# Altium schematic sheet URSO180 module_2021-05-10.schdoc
size 355 x 391 mm
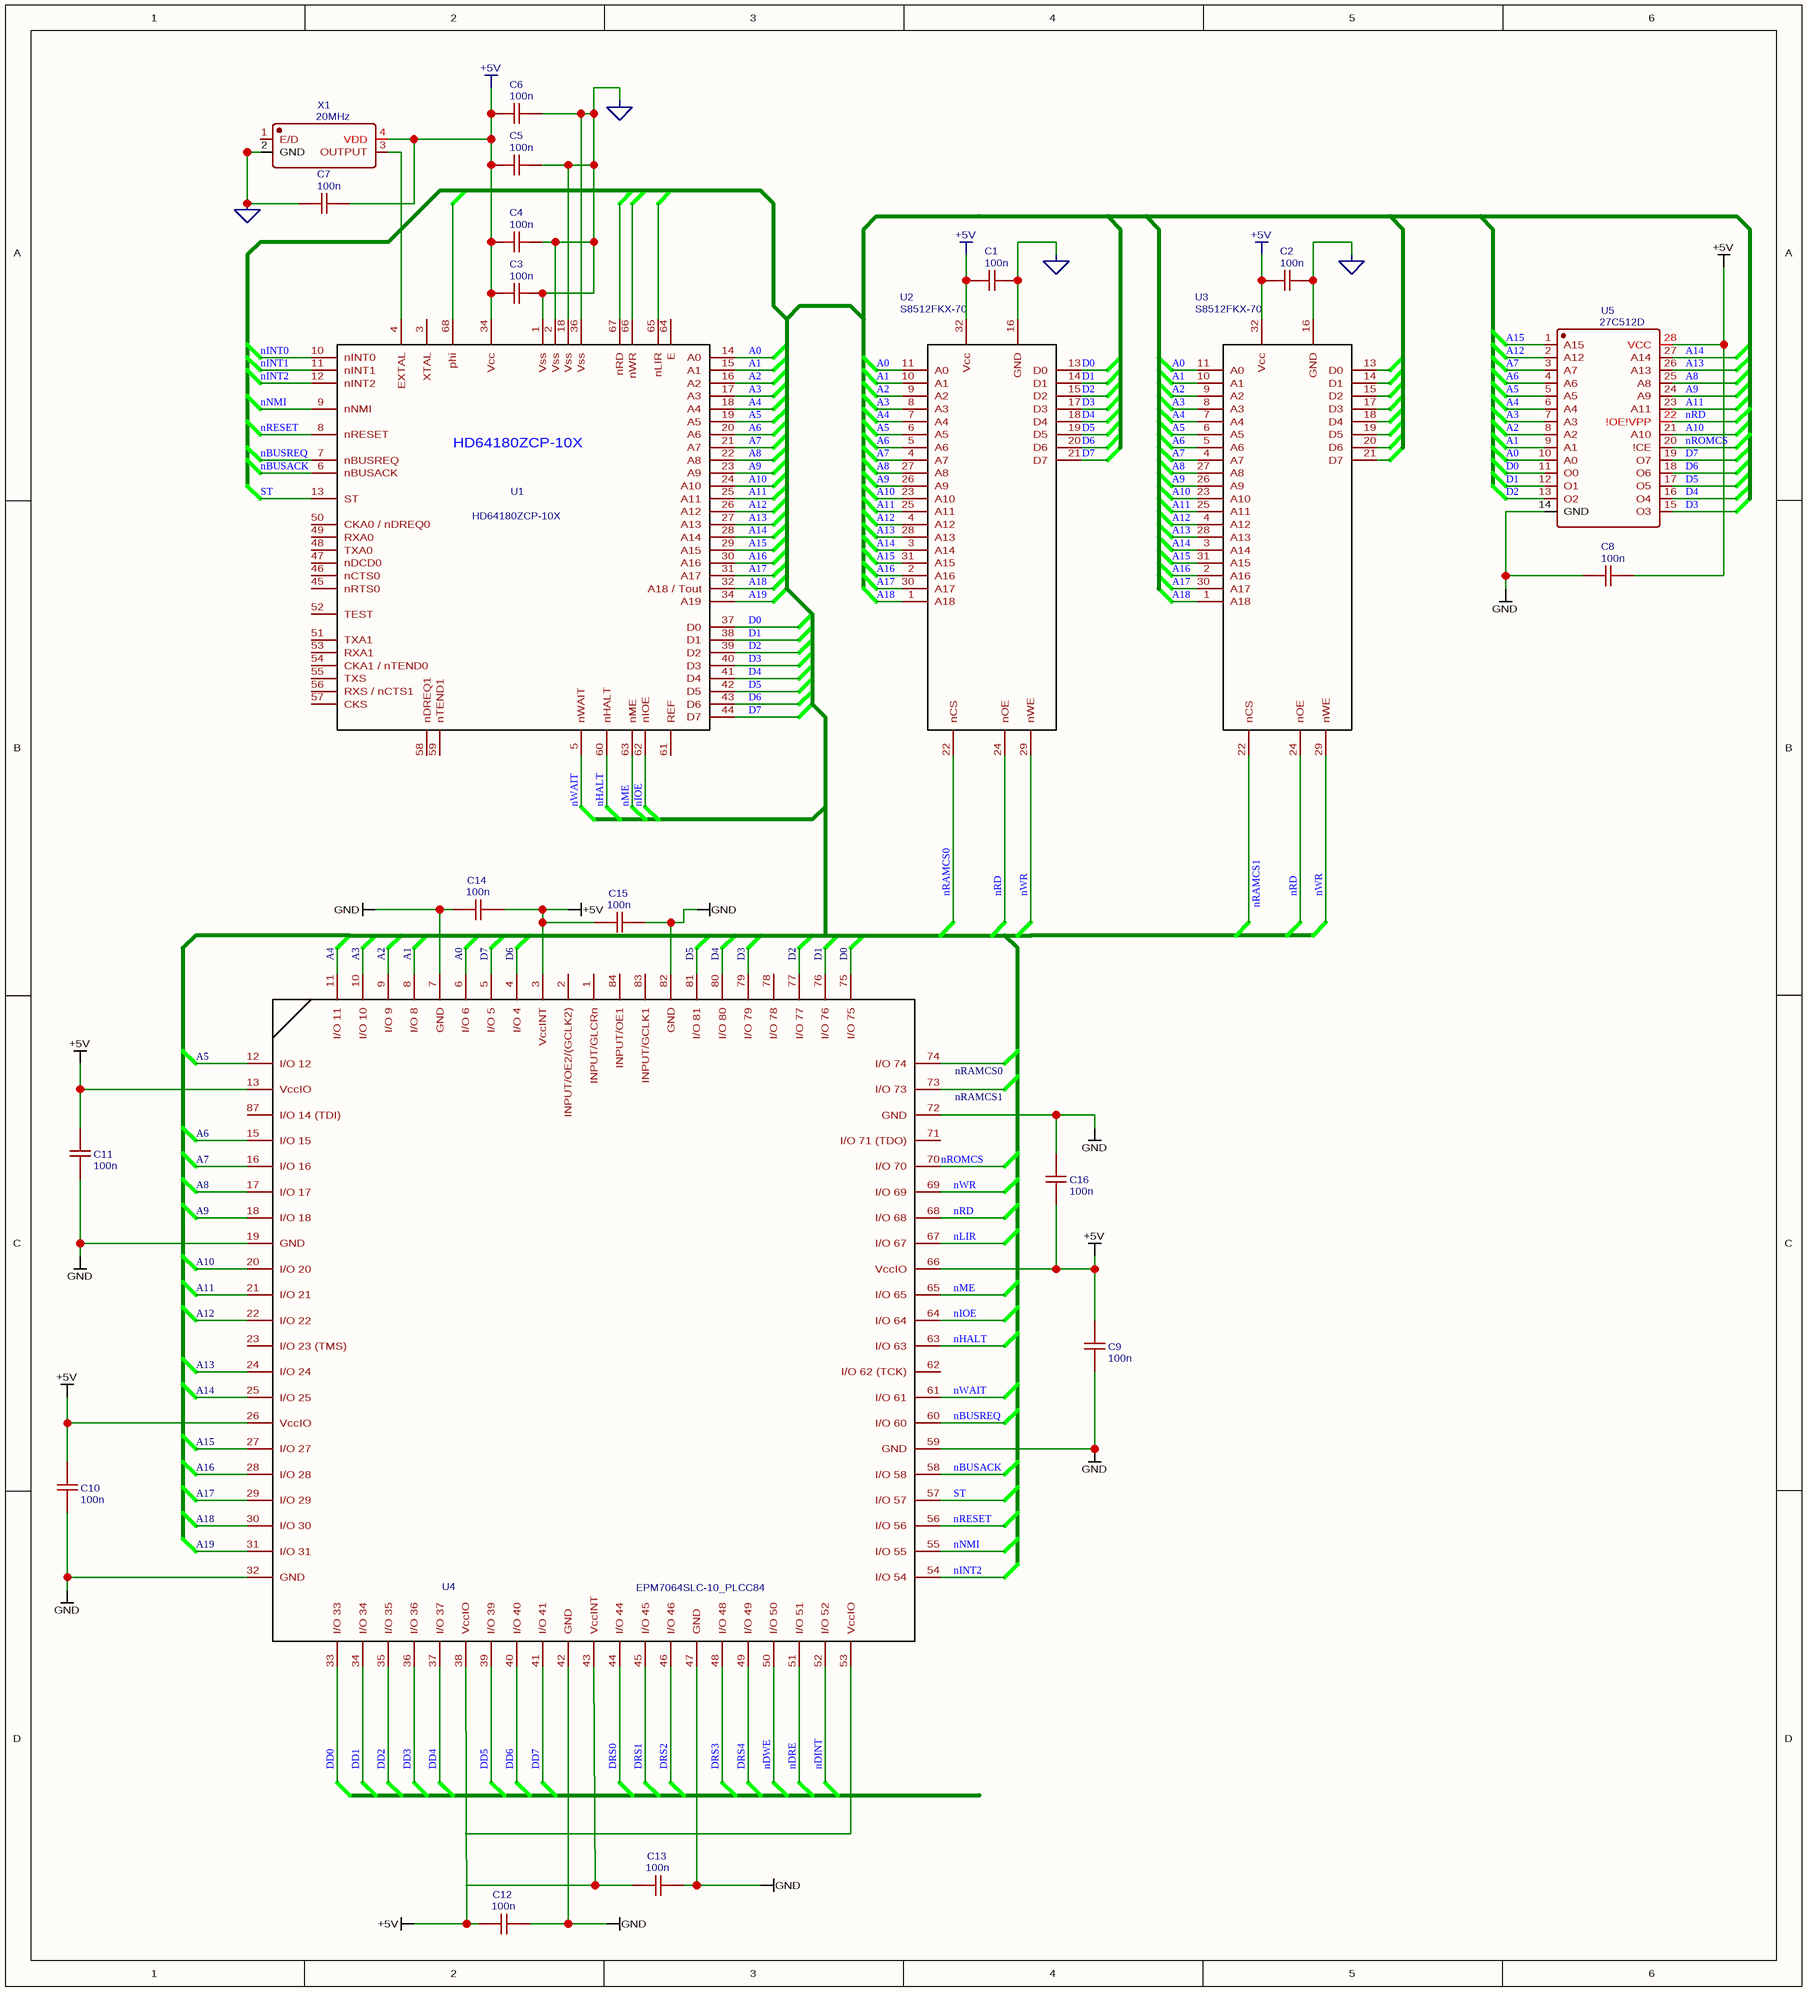
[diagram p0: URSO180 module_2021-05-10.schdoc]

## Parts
C1  100n  [C1]
C2  100n  [C1]
C3  100n  [C1]
C4  100n  [C1]
C5  100n  [C1]
C6  100n  [C1]
C7  100n  [C1]
C8  100n  [C1]
C9  100n  [C1]
C10  100n  [C1]
C11  100n  [C1]
C12  100n  [C1]
C13  100n  [C1]
C14  100n  [C1]
C15  100n  [C1]
C16  100n  [C1]
U1  HD64180ZCP-10X  [PLCC-68]
U2  S8512FKX-70  [DIP]
U3  S8512FKX-70  [DIP]
U4  EPM7064SLC-10_PLCC84  [DIP]
U5  27C512D  [DIP28-600]
X1  20MHz  [OSC-TH_4P-L12.7-W12.7-P7.62-BL]

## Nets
+5V: C1.1 C2.1 C3.1 C4.1 C5.1 C6.1 C7.2 C8.2 C9.2 C10.2 C11.2 C12.2 C14.2 C15.1 C16.1 U1.34(Vcc) U2.32(Vcc) U3.32(Vcc) U4.3(VccINT) U4.13(VccIO) U4.26(VccIO) U4.38(VccIO) U4.66(VccIO) U5.28(VCC) X1.4(VDD)
GND: C1.2 C2.2 C3.2 C4.2 C5.2 C6.2 C7.1 C8.1 C9.1 C10.1 C11.1 C12.1 C13.1 C14.1 C15.2 C16.2 U1.1(Vss) U1.2(Vss) U1.18(Vss) U1.36(Vss) U2.16(GND) U3.16(GND) U4.7(GND) U4.19(GND) U4.32(GND) U4.42(GND) U4.47(GND) U4.59(GND) U4.72(GND) U4.82(GND) U5.14(GND) X1.2(GND)
A0: U1.14(A0) U2.11(A0) U3.11(A0) U4.6(I/O_6) U5.10(A0)
A1: U1.15(A1) U2.10(A1) U3.10(A1) U4.8(I/O_8) U5.9(A1)
A2: U1.16(A2) U2.9(A2) U3.9(A2) U4.9(I/O_9) U5.8(A2)
A3: U1.17(A3) U2.8(A3) U3.8(A3) U4.10(I/O_10) U5.7(A3)
A4: U1.18(A4) U2.7(A4) U3.7(A4) U4.11(I/O_11) U5.6(A4)
A5: U1.19(A5) U2.6(A5) U3.6(A5) U4.12(I/O_12) U5.5(A5)
A6: U1.20(A6) U2.5(A6) U3.5(A6) U4.15(I/O_15) U5.4(A6)
A7: U1.21(A7) U2.4(A7) U3.4(A7) U4.16(I/O_16) U5.3(A7)
A8: U1.22(A8) U2.27(A8) U3.27(A8) U4.17(I/O_17) U5.25(A8)
A9: U1.23(A9) U2.26(A9) U3.26(A9) U4.18(I/O_18) U5.24(A9)
A10: U1.24(A10) U2.23(A10) U3.23(A10) U4.20(I/O_20) U5.21(A10)
A11: U1.25(A11) U2.25(A11) U3.25(A11) U4.21(I/O_21) U5.23(A11)
A12: U1.26(A12) U2.4(A12) U3.4(A12) U4.22(I/O_22) U5.2(A12)
A13: U1.27(A13) U2.28(A13) U3.28(A13) U4.24(I/O_24) U5.26(A13)
A14: U1.28(A14) U2.3(A14) U3.3(A14) U4.25(I/O_25) U5.27(A14)
A15: U1.29(A15) U2.31(A15) U3.31(A15) U4.27(I/O_27) U5.1(A15)
A16: U1.30(A16) U2.2(A16) U3.2(A16) U4.28(I/O_28)
A17: U1.31(A17) U2.30(A17) U3.30(A17) U4.29(I/O_29)
A18: U1.32(A18_/_Tout) U2.1(A18) U3.1(A18) U4.30(I/O_30)
A19: U1.34(A19) U4.31(I/O_31)
D0: U1.37(D0) U2.13(D0) U4.75(I/O_75) U5.11(O0)
D1: U1.38(D1) U2.14(D1) U4.76(I/O_76) U5.12(O1)
D2: U1.39(D2) U2.15(D2) U4.77(I/O_77) U5.13(O2)
D3: U1.40(D3) U2.17(D3) U4.79(I/O_79) U5.15(O3)
D4: U1.41(D4) U2.18(D4) U4.80(I/O_80) U5.16(O4)
D5: U1.42(D5) U2.19(D5) U4.81(I/O_81) U5.17(O5)
D6: U1.43(D6) U2.20(D6) U4.4(I/O_4) U5.18(O6)
D7: U1.44(D7) U2.21(D7) U4.5(I/O_5) U5.19(O7)
DD0: U4.33(I/O_33)
DD1: U4.34(I/O_34)
DD2: U4.35(I/O_35)
DD3: U4.36(I/O_36)
DD4: U4.37(I/O_37)
DD5: U4.39(I/O_39)
DD6: U4.40(I/O_40)
DD7: U4.41(I/O_41)
DRS0: U4.44(I/O_44)
DRS1: U4.45(I/O_45)
DRS2: U4.46(I/O_46)
DRS3: U4.48(I/O_48)
DRS4: U4.49(I/O_49)
nBUSACK: U1.6(nBUSACK) U4.58(I/O_58)
nBUSREQ: U1.7(nBUSREQ) U4.60(I/O_60)
nDINT: U4.52(I/O_52)
nDRE: U4.51(I/O_51)
nDWE: U4.50(I/O_50)
nHALT: U1.60(nHALT) U4.63(I/O_63)
nINT0: U1.10(nINT0)
nINT1: U1.11(nINT1)
nINT2: U1.12(nINT2) U4.54(I/O_54)
nIOE: U1.62(nIOE) U4.64(I/O_64)
nLIR: U4.67(I/O_67)
nME: U1.63(nME) U4.65(I/O_65)
nNMI: U1.9(nNMI) U4.55(I/O_55)
nRAMCS0: U2.22(nCS) U4.74(I/O_74)
nRAMCS1: U3.22(nCS) U4.73(I/O_73)
nRD: U2.24(nOE) U3.24(nOE) U4.68(I/O_68) U5.22(!OE!VPP)
nRESET: U1.8(nRESET) U4.56(I/O_56)
nROMCS: U4.70(I/O_70) U5.20(!CE)
nWAIT: U1.5(nWAIT) U4.61(I/O_61)
nWR: U2.29(nWE) U3.29(nWE) U4.69(I/O_69)
ST: U1.13(ST) U4.57(I/O_57)
NetC13_2: C13.2 U4.43(VccINT)
NetU1_4: U1.4(EXTAL) X1.3(OUTPUT)

Not connected (* = marked no-connect by the designer): U1 3(XTAL) 45(nRTS0) 46(nCTS0) 47(nDCD0) 48(TXA0) 49(RXA0) 50(CKA0_/_nDREQ0) 51(TXA1) 52(TEST) 53(RXA1) 54(CKA1_/_nTEND0) 55(TXS) 56(RXS_/_nCTS1) 57(CKS) 58(nDREQ1) 59(nTEND1) 61(REF) 64(E) 65(nLIR) 66(nWR) 67(nRD) 68(phi); U3 13(D0) 14(D1) 15(D2) 17(D3) 18(D4) 19(D5) 20(D6) 21(D7); U4 1(INPUT/GLCRn) 2(INPUT/OE2/(GCLK2)) 23(I/O_23_(TMS)) 53(VccIO) 62(I/O_62_(TCK)) 71(I/O_71_(TDO)) 78(I/O_78) 83(INPUT/GCLK1) 84(INPUT/OE1) 87(I/O_14_(TDI)); X1 1(E/D)

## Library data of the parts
C1-C16 = 100n: nameAlias: Value(F)
U1 = HD64180ZCP-10X: Contributor: scherer3002; sourceId: UMic5nhzR
U2 U3 = S8512FKX-70: Contributor: scherer3002; sourceId: iow1xrJDV
U4 = EPM7064SLC-10_PLCC84: Contributor: scherer3002; sourceId: 9tcICwOI0
X1 = 20MHz: BOM_Manufacturer: YXC; BOM_Manufacturer Part: O1212D20MEDA4SC; nameAlias: Frequency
